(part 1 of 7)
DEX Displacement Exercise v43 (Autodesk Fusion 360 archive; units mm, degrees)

design "DEX Displacement Exercise" references "rct-lb-perp-pincer-x", "rct-dex-toes", "RCT N17 Blister Mirror", "rct-dex-hearth", "rct-dex-squat", "rct-lb-perp-pincer-t", "rct-lb-gt3-edge-idler", "rct-lb-gt3-endmatter", "dex-fixtures-typefive", "RCT N17 Blister"
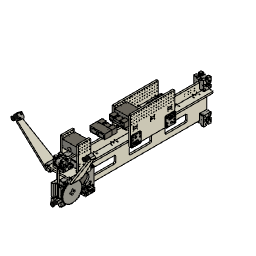
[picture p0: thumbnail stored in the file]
parameter "t_sheet_MAIN" = 6.7 comment "thickness of *most* of the gantry material"
parameter "t_sheet_SECOND" = 6.35 (= "1 / 4 * 1") comment "thickness of the webs"
parameter "od_bearings" = 16
parameter "id_bearings" = 5
parameter "t_bearings" = 5
parameter "p_belt" = 2
parameter "w_belt" = 10
parameter "t_belt" = 1.4
parameter "l_top_belt_to_rail" = 3
parameter "r_cutoutTool" = 2.05 (= "4.1 mm / 2")
parameter "hw_m3_thru" = 3.5
parameter "hw_m3_head" = 5.5
parameter "hw_m3_washer" = 7
parameter "hw_m3_thread" = 2.5
parameter "tab_breather" = 0.2 comment "tab clearance"
parameter "hw_m5_thread" = 4.2
parameter "hw_m5_head" = 8.5
parameter "hw_m5_washer" = 10
parameter "hw_m5_thru" = 5.25
parameter "hw_m6_thru" = 6.5
parameter "hw_m6_head" = 10
parameter "hw_m6_washer" = 12
parameter "l_beltblock" = 15
parameter "hw_plstf6_thread" = 2.94
parameter "hw_plstf6_thru" = 4
parameter "hw_plstf6_head" = 6.86
parameter "hw_plstf6_washer" = 7.92
parameter "hw_m3_flathead" = 6
parameter "hw_m4insert_d" = 6
parameter "hw_m4insert_l" = 4.8
parameter "hw_m4_tappedwj" = 3.3
parameter "hw_m4_thru" = 4.25
parameter "hw_m4_head" = 7
parameter "hw_m4_headheight" = 4
parameter "preload_bearings" = 0.55
parameter "hw_m3insert_d" = 5.4
parameter "hw_m3insert_l" = 3.8
parameter "dist_clearance" = 0.5
parameter "hw_shoulder_headDiameter" = 9
parameter "hw_shoulder_headHeight" = 4
parameter "l_travel" = 385 comment "will be rounded to 10s"
parameter "User Parameter" = 0 (= "min 10")
parameter "nh_rail_width" = "nh_gantry_width - 3"
parameter "l_shoulder_thread" = 10
parameter "hw_n6_thru" = 4.064
parameter "hw_n6_thread" = 3.1
parameter "hw_n6_flathead" = 6.6548
parameter "hw_n6_head" = 6.858
parameter "carriage_offsets" = 0.25
parameter "hw_momentPin_reald" = 3.683
parameter "d285" = 2
parameter "d344" = 3.5
parameter "d482" = 3.35 (= "t_sheet_MAIN / 2")
parameter "d578" = 0.5
parameter "d683" = 3.683 (= "hw_momentPin_reald")
parameter "d689" = 0.5
parameter "d698" = 5
parameter "d705" = 3.5415 (= "d683 / 2 + 1.7 mm")
parameter "d837" = 0.25
parameter "d1052" = 1.5
parameter "d1488" = 23.5592 (= "d1487 / 2 + d1486 / 2 + 2.4 mm")
parameter "d1496" = 0.3 (= "d1494")
sketch "Basics" plane through (0, 0, 0) normal (0, 1, 0) x axis (1, 0, 0)
  line L1 (-3.35, -35.65) -> (3.35, -35.65)
  line L2 (-3.35, 98.35) -> (-3.35, -35.65)
  line L3 (3.35, 98.35) -> (-3.35, 98.35)
  line L4 (3.35, -35.65) -> (3.35, 98.35)
  line L5 (-29.1, -3.35) -> (-3.35, -3.35)
  line L6 (-29.1, 3.35) -> (-29.1, -3.35)
  line L7 (-3.35, 3.35) -> (-29.1, 3.35)
  line L8 (-3.35, -3.35) -> (-3.35, 3.35)
  line L9 (-19.35, -35.15) -> (-3.35, -35.15)
  line L10 (-19.35, -30.15) -> (-19.35, -35.15)
  line L11 (-3.35, -30.15) -> (-19.35, -30.15)
  line L12 (-3.35, -35.15) -> (-3.35, -30.15)
  line L13 (19.35, -30.15) -> (3.35, -30.15)
  line L14 (19.35, -35.15) -> (19.35, -30.15)
  line L15 (3.35, -35.15) -> (19.35, -35.15)
  line L16 (3.35, -30.15) -> (3.35, -35.15)
  line L17 (2.5, -35.65) -> (-2.5, -35.65)
  line L18 (2.5, -51.65) -> (2.5, -35.65)
  line L19 (-2.5, -51.65) -> (2.5, -51.65)
  line L20 (-2.5, -35.65) -> (-2.5, -51.65)
  line L21 (-30.1, -36.65) -> (19.9, -36.65)
  line L22 (-30.1, -43.35) -> (-30.1, -36.65)
  line L23 (19.9, -43.35) -> (-30.1, -43.35)
  line L24 (19.9, -36.65) -> (19.9, -43.35)
  line L25 (-30.1, -93.35) -> (-36.8, -93.35)
  line L26 (-30.1, 19.9) -> (-30.1, -93.35)
  line L27 (-36.8, 19.9) -> (-30.1, 19.9)
  line L28 (-36.8, -93.35) -> (-36.8, 19.9)
  line L29 (-45.1, 2.5) -> (-29.1, 2.5)
  line L30 (-45.1, -2.5) -> (-45.1, 2.5)
  line L31 (-29.1, -2.5) -> (-45.1, -2.5)
  line L32 (-29.1, 2.5) -> (-29.1, -2.5)
  line L33 (-23.6, 3.35) -> (-28.6, 3.35)
  line L34 (-23.6, 19.35) -> (-23.6, 3.35)
  line L35 (-28.6, 19.35) -> (-23.6, 19.35)
  line L36 (-28.6, 3.35) -> (-28.6, 19.35)
  line L37 (-23.6, -3.35) -> (-28.6, -3.35)
  line L38 (-23.6, -19.35) -> (-23.6, -3.35)
  line L39 (-28.6, -19.35) -> (-23.6, -19.35)
  line L40 (-28.6, -3.35) -> (-28.6, -19.35)
  line L41 (-15.85, -25.65) -> (-15.85, -30.15)
  line L42 (-6.85, -25.65) -> (-15.85, -25.65)
  line L43 (-6.85, -30.15) -> (-6.85, -25.65)
  point P10 (-3.35, -35.15)
  point P14 (3.35, -30.15)
  point P22 (0, -35.65)
  point P35 (-28.6, 3.35)
  point P39 (-29.1, 0)
  point P40 (-28.6, -3.35)
  point P37 (-23.6, 19.35)
  point P44 (-15.85, -30.15)
  point P47 (-6.85, -30.15)
  point P48 (-11.35, -25.65)
  point P49 (-11.35, -30.15)
  point P9 (-3.35, 3.35)
  point P1 (0, 0)
  point P25 (-30.1, -43.35)
  point P50 (19.9, -40)
  point P7 (-29.1, -3.35)
  point P8 (-29.1, 3.35)
  point P11 (-19.35, -35.15)
  point P12 (-19.35, -30.15)
  point P13 (-3.35, -30.15)
  point P3 (-3.35, -35.65)
  point P45 (-15.85, -25.65)
  point P46 (-6.85, -25.65)
  point P26 (19.9, -43.35)
  point P19 (2.5, -35.65)
  horizontal L1
  vertical L2
  horizontal L3
  vertical L4
  horizontal L5
  vertical L6
  horizontal L7
  horizontal L9
  vertical L10
  horizontal L11
  vertical L12
  coincident L2 P10
  horizontal L13
  vertical L14
  horizontal L15
  vertical L16
  coincident L4 P14
  horizontal L17
  vertical L18
  horizontal L19
  vertical L20
  equal L10 L19
  equal L10 L14
  equal L9 L20
  equal L9 L15
  coincident P10 L15
  midpoint L17 P22
  midpoint L1 P22
  horizontal L21
  vertical L22
  horizontal L23
  vertical L24
  vertical L26
  horizontal L27
  vertical L28
  equal L6 L27
  equal L6 L22
  horizontal L29
  vertical L30
  horizontal L31
  vertical L32
  horizontal L33
  vertical L34
  horizontal L35
  vertical L36
  equal L30 L35
  equal L10 L35
  equal L29 L36
  equal L11 L36
  coincident L7 P35
  midpoint L32 P39
  midpoint L6 P39
  horizontal L37
  vertical L38
  horizontal L39
  vertical L40
  equal L35 L39
  equal L34 L40
  coincident L5 P40
  coincident P37 L38
  vertical L8
  coincident L11 P44
  perpendicular L11 L41
  perpendicular L41 L42
  coincident L11 P47
  perpendicular L11 L43
  midpoint L42 P48
  midpoint L11 P49
  vertical P48 P49
  coincident L2 P9
  vertical P1 P22
  horizontal P1 P39
  coincident P25 L26
  midpoint L24 P50
  horizontal L25
  dimension "d925" distance P7 P8 = 6.7 (= "t_sheet_MAIN")
  dimension "d926" distance L2 L4 = 6.7 (= "t_sheet_MAIN")
  dimension "d928" distance P11 P12 = 5 (= "t_bearings")
  dimension "d929" distance P12 P13 = 16 (= "od_bearings")
  dimension "d930" distance P3 L9 = 0.5
  dimension "d932" distance P11 L21 = 1.5 (= "d1052")
  dimension "d935" distance P8 L36 = 0.5
  dimension "d936" distance L26 L36 = 1.5 (= "d1052")
  dimension "d1049" distance P44 P45 = 4.5
  dimension "d1050" distance P45 P46 = 9
  dimension "d1055" distance P22 P26 = 19.9
  dimension "d1056" distance L27 P39 = 19.9
  dimension "d1099" distance L3 P9 = 95
  dimension "d1213" distance P26 L26 = 50
  dimension "d1214" distance P25 L25 = 50
  dimension "d1215" distance P39 P50 = 40
  dimension "d1241" distance L2 L26 = 26.75
  dimension "d1583" distance P1 P39 = 29.1
  dimension "d1584" distance P1 P19 = 35.65
  dimension "d1012" OffsetX = 0
  dimension "d1013" OffsetY = 0
  dimension "d1014" OffsetZ = 0
  dimension "d1015" AngleZ = 0
  dimension "d1036" OffsetX = 0
  dimension "d1037" OffsetY = 0
  dimension "d1038" OffsetZ = 0
  dimension "d1039" AngleZ = 0
  dimension "d1061" OffsetX = 0
  dimension "d1062" OffsetY = 0
  dimension "d1063" OffsetZ = 0
  dimension "d1064" AngleZ = 0
  dimension "d900" distance = 6
  dimension "d902" distance = 3.7 (= "2 mm + 1.2 mm + 0.5 mm")
  dimension "d903" distance = 1
  dimension "d904" distance = 8
  dimension "d905" distance = 2.54
  dimension "d906" distance = 2.54
  dimension "d907" distance = 2.54
  dimension "d908" Side1Offset = 0
  dimension "d909" TaperAngle = 0
  dimension "d910" ProfileOffset = 0
  dimension "d911" Side1Offset = 0
  dimension "d912" TaperAngle = 0
  dimension "d913" leftDistance = 1.5
  dimension "d915" distance = 5.65
  dimension "d916" distance = 14.65
  dimension "d917" distance = 14.65
  dimension "d918" Side1Offset = 0
  dimension "d919" TaperAngle = 0
  dimension "d920" ChordLen = 4
  dimension "d921" ChordLen = 1
  dimension "d923" distance = 2.54
  dimension "d924" Radius = 2
  dimension "d729" diameter = 4
  dimension "d730" diameter = 6 (= "hw_m4insert_d")
  dimension "d731" diameter = 16 (= "od_bearings")
  dimension "d732" distance = 1
  dimension "d733" distance = 0.25
  dimension "d734" AlongDistance = -26
  dimension "d735" TaperAngle = 0
  dimension "d736" ProfileOffset = 0.5
  dimension "d737" AlongDistance = 5 (= "t_bearings")
  dimension "d738" TaperAngle = 0
  dimension "d739" distance = 6
  dimension "d740" ProfileOffset = 0
  dimension "d741" Side1Offset = 0
  dimension "d742" TaperAngle = 0
  dimension "d743" Radius = 4
  dimension "d744" distance = -1
  dimension "d745" AlongDistance = 32
  dimension "d746" TaperAngle = 0
  dimension "d747" distance = 0.5
  dimension "d748" distance = 1
  dimension "d749" ProfileOffset = 0
  dimension "d750" AlongDistance = 3
  dimension "d751" TaperAngle = 0
  dimension "d752" ProfileOffset = 0
  dimension "d753" Side1Offset = 0
  dimension "d754" TaperAngle = 0
  dimension "d755" Side1Offset = 0
  dimension "d756" TaperAngle = 0
  dimension "d757" ProfileOffset = 0
  dimension "d758" Side1Offset = 0
  dimension "d759" TaperAngle = 0
  dimension "d760" AlongDistance = 12
  dimension "d761" TaperAngle = 0
  dimension "d762" AlongDistance = -37
  dimension "d763" TaperAngle = 0
  dimension "d764" Side1Offset = 0.5
  dimension "d765" TaperAngle = 0
  dimension "d767" Radius = 3
  dimension "d768" Radius = 2
  dimension "d770" Radius = 3
  dimension "d771" Radius = 3
  dimension "d772" distance = 3
  dimension "d773" distance = 3
  dimension "d774" Radius = 1
  dimension "d775" Radius = 0.5
  dimension "d776" Radius = 2
  dimension "d777" diameter = 5.4 (= "hw_m3insert_d")
  dimension "d778" diameter = 3.5 (= "hw_m3_thru")
  dimension "d779" Side1Offset = 0
  dimension "d780" TaperAngle = 0
  dimension "d781" Side1Offset = 0
  dimension "d782" TaperAngle = 0
  dimension "d783" Radius = 2
  dimension "d784" Radius = 2
  dimension "d785" Radius = 2
  dimension "d786" Radius = 3
  dimension "d788" Radius = 0.5
  dimension "d789" distance = 12
  dimension "d790" distance = 2
  dimension "d791" angle = 45
  dimension "d793" Radius = 2
  dimension "d794" Radius = 2
  dimension "d795" Radius = 1
  dimension "d797" Radius = 2
  dimension "d798" Radius = 1
  dimension "d799" Radius = 2
  dimension "d800" Radius = 4.5
  dimension "d801" distance = 0.275 (= "preload_bearings / 2")
  dimension "d803" distance = -0.5
  dimension "d806" distance = 3
  dimension "d807" AlongDistance = -60
  dimension "d808" distance = 3.8274 (= "d430 / 2")
  dimension "d809" distance = 0.423 (= "1 mm - 0.577 mm")
  dimension "d810" distance = 0.5
  dimension "d813" Side1Offset = 0
  dimension "d814" TaperAngle = 0
  dimension "d815" distance = 0.1
  dimension "d816" distance = 1.75
  dimension "d818" distance = 35
  dimension "d820" distance = 5
  dimension "d821" distance = 5
  dimension "d822" diameter = 4.064 (= "hw_n6_thru")
  dimension "d823" diameter = 6.6548 (= "hw_n6_flathead")
  dimension "d824" distance = 0.6
  dimension "d825" distance = 0.6 (= "d824")
  dimension "d827" TaperAngle = 0
  dimension "d828" diameter = 3.1 (= "hw_n6_thread")
  dimension "d829" Side1Offset = 0
  dimension "d830" TaperAngle = 0
  dimension "d831" distance = 4
  dimension "d832" distance = 4.477 (= "d833")
  dimension "d833" distance = 4.477 (= "d477")
  dimension "d836" diameter = 6.6548 (= "hw_n6_flathead")
  dimension "d839" Side1Offset = 0
  dimension "d840" TaperAngle = 0
  dimension "d841" distance = 0.9
  dimension "d842" angle = 50
  dimension "d843" angle = 50
  dimension "d844" distance = 8
  dimension "d845" distance = 5
  dimension "d846" diameter = 4.5
  dimension "d847" AlongDistance = -7
  dimension "d848" TaperAngle = 0
  dimension "d849" leftDistance = 0.75
  dimension "d850" ProfileOffset = 0
  dimension "d851" Side1Offset = 0
  dimension "d852" TaperAngle = 0
  dimension "d853" ProfileOffset = 0
  dimension "d854" Side1Offset = 0
  dimension "d855" TaperAngle = 0
  dimension "d856" distance = 12.7
  dimension "d857" leftDistance = 1.5
  dimension "d858" distance = 1.5454
  dimension "d859" Radius = 4
  dimension "d860" Radius = 2
  dimension "d861" Radius = 2
  dimension "d862" Radius = 4
  dimension "d863" Radius = 2
  dimension "d864" Radius = 35
  dimension "d865" Radius = 4
  dimension "d866" Radius = 1
  dimension "d869" Side1Offset = 0
  dimension "d870" TaperAngle = 0
  dimension "d872" distance = 1.5
  dimension "d873" leftDistance = 1.5
  dimension "d874" Radius = 2
  dimension "d885" distance = 27.775
  dimension "d886" distance = 30.275 (= "30 mm + preload_bearings / 2")
  dimension "d889" diameter = 3.3 (= "hw_m4_tappedwj")
  dimension "d890" distance = 5
  dimension "d891" distance = 10.275 (= "10 mm + preload_bearings / 2")
  dimension "d893" TaperAngle = 0
  dimension "d894" distance = 17.5
  dimension "d895" distance = 27.5
  dimension "d896" distance = 0.2
  dimension "d897" distance = 0.2 (= "d896")
extrude "Extrude1" new body sketch "Basics" profile of L3 L5 L6 L7 L8 along normal blind 600 (= "l_actual_complete") OffsetX 0 OffsetY 0 OffsetZ 0 AngleZ 0 OffsetX 0 OffsetY 0 OffsetZ 0 AngleZ 0 OffsetX 0 OffsetY 0 OffsetZ 0 AngleZ 0 OffsetX 0 OffsetY 0 OffsetZ 0 AngleZ 0 bodies "dex-rail_left-wing"
extrude "Extrude2" new body sketch "Basics" profile of L1 L2 L3 L4 L5 along normal blind 600 (= "l_actual_complete")
extrude "Extrude1" new body sketch "Basics" profile of L21 L25 L26 L27 L28 along normal blind 90 (= "( nh_gantry_length * 10 ) * 1 mm / 2") OffsetX 0 OffsetY 0 OffsetZ 0 AngleZ 0
extrude "Extrude2" new body sketch "Basics" profile of L21 L22 L23 L24 L25 along normal blind 90 (= "( nh_gantry_length * 10 ) * 1 mm / 2")
ground "Ground1"
joint "Assemble4" alignAngle 0 alignOffsetX 0 alignOffsetY 0 alignOffsetZ 0 DistanceMinimum 95 DistanceMaximum 390 (= "l_actual_complete - ( nh_gantry_length * 10 ) * 1 mm - 30 mm")
sketch "Sketch2" plane through (0, -166.9996, 43.35) normal (0, 0, 1) x axis (-1, 0, 0)
  line L1 (-19.9, -166.9996) -> (30.1, -166.9996)
  line L2 (-19.9, -256.9996) -> (-19.9, -166.9996)
  line L3 (30.1, -256.9996) -> (-19.9, -256.9996)
  line L4 (30.1, -166.9996) -> (30.1, -256.9996)
  line L5 (0, -256.9996) -> (0, -166.9996)
  line L6 (20, -194.9996) -> (-19.9, -194.9996)
  line L7 (20, -218.9996) -> (20, -194.9996)
  line L8 (2, -218.9996) -> (20, -218.9996)
  line L9 (2, -224.9996) -> (2, -218.9996)
  line L10 (-12, -224.9996) -> (2, -224.9996)
  line L11 (-12, -218.9996) -> (-12, -224.9996)
  line L12 (-19.9, -218.9996) -> (-12, -218.9996)
  line L13 (-30.1, -256.9996) -> (-19.9, -256.9996)
  line L14 (-30.1, -166.9996) -> (-30.1, -256.9996)
  line L15 (-19.9, -166.9996) -> (-30.1, -166.9996)
  line L16 (7.5, -186.9996) -> (7.5, -166.9996)
  line L17 (-7.5, -186.9996) -> (7.5, -186.9996)
  line L18 (-7.5, -166.9996) -> (-7.5, -186.9996)
  line L19 (-20.4, -218.9996) -> (-19.9, -218.9996)
  line L20 (-20.4, -194.9996) -> (-20.4, -218.9996)
  line L21 (-19.9, -194.9996) -> (-20.4, -194.9996)
  line L22 (16, -174.9996) -> (16, -166.9996)
  line L23 (8, -174.9996) -> (16, -174.9996)
  line L24 (8, -186.9996) -> (8, -174.9996)
  line L25 (-8, -186.9996) -> (8, -186.9996)
  line L26 (-8, -174.9996) -> (-8, -186.9996)
  line L27 (-16, -174.9996) -> (-8, -174.9996)
  line L28 (-16, -166.9996) -> (-16, -174.9996)
  circle C1 centre (5, -191.9996) radius 1.575
  circle C2 centre (15, -191.9996) radius 1.575
  circle C3 centre (-5, -191.9996) radius 1.575
  circle C4 centre (-15, -191.9996) radius 1.575
  circle C5 centre (-15, -221.9996) radius 1.575
  circle C6 centre (5, -221.9996) radius 1.575
  circle C7 centre (15, -221.9996) radius 1.575
  circle C8 centre (12, -181.9996) radius 1.575
  circle C9 centre (12, -171.9996) radius 1.575
  circle C10 centre (12, -181.9996) radius 2.7
  circle C11 centre (-12, -181.9996) radius 1.575
  circle C12 centre (-12, -171.9996) radius 1.575
  point P8 (0, -166.9996)
  point P9 (0, -256.9996)
  point P1 (0, 0)
  point P6 (5, -191.9996)
  point P7 (15, -191.9996)
  point P10 (-5, -191.9996)
  point P11 (-15, -191.9996)
  point P12 (-15, -221.9996)
  point P13 (5, -221.9996)
  point P14 (15, -221.9996)
  point P15 (-19.9, -194.9996)
  point P22 (-19.9, -218.9996)
  point P18 (2, -218.9996)
  point P4 (-19.9, -256.9996)
  point P23 (-19.9, -256.9996)
  point P3 (-19.9, -166.9996)
  point P26 (-19.9, -166.9996)
  point P27 (7.5, -166.9996)
  point P30 (-7.5, -166.9996)
  point P31 (0, -186.9996)
  point P33 (12, -171.9996)
  point P34 (12, -181.9996)
  point P39 (-19.9, -194.9996)
  point P40 (16, -166.9996)
  point P47 (-16, -166.9996)
  point P48 (0, -186.9996)
  point P42 (8, -174.9996)
  point P2 (30.1, -166.9996)
  point P28 (7.5, -186.9996)
  point P29 (-7.5, -186.9996)
  point P32 (12, -181.9996)
  point P37 (-20.4, -218.9996)
  point P41 (16, -174.9996)
  point P43 (8, -186.9996)
  coincident L1 P8
  coincident L3 P9
  perpendicular L3 L5
  coincident P1 L5
  horizontal P6 P7
  equal C1 C2
  horizontal P6 P10
  horizontal P6 P11
  equal C1 C7
  equal C1 C6
  equal C1 C5
  equal C1 C3
  equal C1 C4
  vertical P11 P12
  vertical P6 P13
  vertical P7 P14
  horizontal P13 P14
  horizontal P12 P14
  coincident L2 P15
  perpendicular L2 L6
  perpendicular L6 L7
  perpendicular L7 L8
  perpendicular L8 L9
  perpendicular L9 L10
  perpendicular L10 L11
  coincident L2 P22
  perpendicular L2 L12
  coincident P18 L12
  coincident P4 P23
  perpendicular L2 L13
  perpendicular L13 L14
  perpendicular L14 L15
  coincident P3 P26
  coincident L1 P27
  perpendicular L1 L16
  perpendicular L16 L17
  coincident L1 P30
  perpendicular L1 L18
  midpoint L17 P31
  vertical P8 P31
  equal C1 C8
  equal C8 C9
  concentric C8 C10
  vertical P33 P34
  symmetric L5 C8 C11
  symmetric L5 C9 C12
  perpendicular L2 L19
  perpendicular L19 L20
  perpendicular L20 L21
  coincident P15 P39
  coincident L1 P40
  perpendicular L1 L22
  perpendicular L16 L23
  perpendicular L23 L24
  perpendicular L5 L25
  perpendicular L25 L26
  perpendicular L26 L27
  coincident L1 P47
  perpendicular L1 L28
  midpoint L25 P48
  coincident L5 P48
  coincident P42 L27
  dimension "d1100" distance P6 L5 = 5
  dimension "d1101" diameter C1 = 3.15
  dimension "d1102" distance P6 P7 = 10
  dimension "d1103" distance P6 P8 = 25
  dimension "d1104" distance P8 P10 = 5
  dimension "d1105" distance P10 P11 = 10
  dimension "d1106" distance P7 P14 = 30
  dimension "d1107" distance P13 L9 = 3
  dimension "d1108" distance P13 L10 = 3
  dimension "d1109" distance P13 L8 = 3
  dimension "d1110" distance P12 L11 = 3
  dimension "d1111" distance P14 L7 = 5
  dimension "d1112" distance P7 L6 = 3
  dimension "d1218" distance P2 L14 = 60.2
  dimension "d1321" distance P28 P29 = 15
  dimension "d1322" distance P29 P30 = 20
  dimension "d1323" distance P32 P33 = 10
  dimension "d1324" distance L1 P33 = 5
  dimension "d1325" diameter C10 = 5.4 (= "hw_m3insert_d")
  dimension "d1326" distance L5 P32 = 12
  dimension "d1387" distance P22 P37 = 0.5
  dimension "d1449" distance P31 L24 = 8
  dimension "d1450" distance P40 P41 = 8
  dimension "d1451" distance P8 L22 = 16
  dimension "d1452" distance P8 L28 = 16 (= "d1451")
  dimension "d1453" distance P42 P43 = 12
extrude "Extrude3" cut sketch "Sketch2" profile of L2 C1 C2 C3 C4 C5 C6 C7 L6 L7 L8 L9 L10 L11 L12 C8 C9 C11 C12 no distance stored
extrude "Extrude5" add sketch "Sketch2" profile of L2 L13 L14 L15 L19 L20 L21 no distance stored
sketch "Sketch3" plane through (-36.8, 0, 0) normal (-1, 0, 0) x axis (0, -1, 0)
  line L1 (0, 93.35) -> (0, -19.9)
  line L2 (-90, 93.35) -> (0, 93.35)
  line L3 (-90, -19.9) -> (-90, 93.35)
  line L4 (0, -19.9) -> (-90, -19.9)
  line L5 (0, 0) -> (-90, 0)
  line L6 (-5, 15) -> (-5, -15)
  line L7 (-32, -12) -> (-38, -12)
  line L8 (-32, -19.9) -> (-32, -12)
  line L9 (-38, 12) -> (-38, -12)
  line L10 (-32, 12) -> (-38, 12)
  line L11 (-32, 20.5) -> (-32, 12)
  line L12 (-8, 20.5) -> (-32, 20.5)
  line L13 (-8, -19.9) -> (-8, 20.5)
  line L14 (-90, 40) -> (0, 40)
  line L15 (-90, 36.65) -> (-90, 43.35)
  line L16 (-12.5, 36.65) -> (-27.5, 36.65)
  line L17 (-12.5, 43.35) -> (-12.5, 36.65)
  line L18 (-27.5, 43.35) -> (-12.5, 43.35)
  line L19 (-27.5, 36.65) -> (-27.5, 43.35)
  line L20 (-12.5, 32.5) -> (-27.5, 32.5)
  line L21 (-12.5, 47.5) -> (-12.5, 32.5)
  line L22 (-27.5, 47.5) -> (-12.5, 47.5)
  line L23 (-27.5, 32.5) -> (-27.5, 47.5)
  line L24 (-82.5, 36.65) -> (-97.5, 36.65)
  line L25 (-82.5, 43.35) -> (-82.5, 36.65)
  line L26 (-97.5, 43.35) -> (-82.5, 43.35)
  line L27 (-97.5, 36.65) -> (-97.5, 43.35)
  line L28 (-82.5, 32.5) -> (-97.5, 32.5)
  line L29 (-82.5, 47.5) -> (-82.5, 32.5)
  line L30 (-97.5, 47.5) -> (-82.5, 47.5)
  line L31 (-97.5, 32.5) -> (-97.5, 47.5)
  circle C1 centre (-5, 5) radius 1.575
  circle C2 centre (-5, 15) radius 1.575
  circle C3 centre (-35, 15) radius 1.575
  circle C4 centre (-35, -15) radius 1.575
  circle C5 centre (-5, -15) radius 1.575
  circle C6 centre (-5, -5) radius 1.575
  circle C7 centre (-12.5, 32.5) radius 1.575
  circle C8 centre (-27.5, 32.5) radius 1.575
  circle C9 centre (-27.5, 47.5) radius 1.575
  circle C10 centre (-12.5, 47.5) radius 1.575
  circle C11 centre (-82.5, 32.5) radius 1.575
  circle C12 centre (-97.5, 32.5) radius 1.575
  circle C13 centre (-97.5, 47.5) radius 1.575
  circle C14 centre (-82.5, 47.5) radius 1.575
  point P6 (-90, 0)
  point P7 (0, 0)
  point P1 (0, 0)
  point P12 (-5, -15)
  point P14 (-5, -15)
  point P9 (-5, 15)
  point P15 (-5, 15)
  point P16 (-5, 0)
  point P13 (-5, -5)
  point P8 (-5, 5)
  point P11 (-35, -15)
  point P10 (-35, 15)
  point P19 (-32, -19.9)
  point P24 (-8, -19.9)
  point P25 (0, 40)
  point P26 (-90, 40)
  point P33 (-27.5, 40)
  point P37 (-12.5, 47.5)
  point P40 (-12.5, 47.5)
  point P35 (-27.5, 32.5)
  point P38 (-27.5, 32.5)
  point P34 (-12.5, 32.5)
  point P39 (-12.5, 32.5)
  point P36 (-27.5, 47.5)
  point P41 (-27.5, 47.5)
  point P46 (-97.5, 32.5)
  point P47 (-82.5, 32.5)
  point P50 (-97.5, 40)
  point P51 (-97.5, 40)
  point P32 (-27.5, 43.35)
  point P52 (-82.5, 32.5)
  point P53 (-97.5, 32.5)
  point P49 (-97.5, 47.5)
  point P54 (-97.5, 47.5)
  point P48 (-82.5, 47.5)
  point P55 (-82.5, 47.5)
  point P18 (-32, -12)
  point P56 (-90, 47.5)
  point P57 (-20, 32.5)
  point P29 (-27.5, 36.65)
  point P30 (-12.5, 36.65)
  coincident L3 P6
  coincident L1 P7
  perpendicular L1 L5
  coincident P1 L5
  coincident P12 P14
  vertical L6
  coincident P9 P15
  midpoint L6 P16
  coincident L5 P16
  coincident P13 L6
  coincident P8 L6
  equal C5 C6
  equal C1 C5
  equal C2 C5
  equal C4 C5
  equal C3 C5
  horizontal P11 P12
  horizontal P9 P10
  vertical P10 P11
  parallel L5 L7
  coincident L4 P19
  perpendicular L4 L8
  perpendicular L5 L9
  perpendicular L9 L10
  perpendicular L5 L11
  perpendicular L11 L12
  coincident L4 P24
  perpendicular L4 L13
  coincident L1 P25
  coincident L3 P26
  perpendicular L3 L14
  midpoint P26 L15
  horizontal L16
  vertical L17
  horizontal L18
  vertical L19
  midpoint L19 P33
  coincident L14 P33
  horizontal L20
  vertical L21
  horizontal L22
  vertical L23
  coincident P37 P40
  coincident P35 P38
  equal C8 C9
  equal C7 C8
  equal C8 C10
  coincident P34 P39
  coincident P36 P41
  coincident L17 P34
  horizontal L24
  vertical L25
  horizontal L26
  vertical L27
  horizontal L28
  vertical L29
  horizontal L30
  vertical L31
  coincident L27 P46
  coincident L25 P47
  midpoint L27 P50
  midpoint L31 P51
  coincident P50 P51
  coincident P32 L26
  coincident P36 L30
  equal L22 L30
  coincident L14 P51
  coincident P47 P52
  coincident P46 P53
  coincident P49 P54
  coincident P48 P55
  equal C8 C11
  equal C11 C12
  equal C11 C13
  equal C11 C14
  coincident P18 L11
  midpoint L30 P56
  coincident L3 P56
  midpoint L20 P57
  dimension "d1159" distance P12 P13 = 10
  dimension "d1160" distance P7 L6 = 5
  dimension "d1161" distance P8 P9 = 10
  dimension "d1162" diameter C5 = 3.15
  dimension "d1163" distance P13 P16 = 5
  dimension "d1164" distance P9 P10 = 30
  dimension "d1165" distance P11 L8 = 3
  dimension "d1166" distance P11 L7 = 3
  dimension "d1167" distance P11 L9 = 3
  dimension "d1170" distance P10 L12 = 5.5
  dimension "d1171" distance P8 L13 = 3
  dimension "d1269" distance P29 P30 = 15
  dimension "d1270" distance P29 P32 = 6.7 (= "t_sheet_MAIN")
  dimension "d1272" distance P38 P41 = 15
  dimension "d1273" distance P38 P39 = 15
  dimension "d1274" diameter C8 = 3.15
  dimension "d1276" distance L14 L20 = 7.5
  dimension "d1301" = 40
  dimension "d1388" distance P10 L10 = 3
  dimension "d1700" distance L1 P57 = 20
extrude "Extrude4" cut sketch "Sketch3" profile of L4 C1 C2 C3 C4 C5 C6 L7 L8 L9 L10 L11 L12 L13 no distance stored
sketch "Sketch6" plane through (0, 0, 43.35) normal (0, 0, 1) x axis (-1, 0, 0)
  line L1 (30.1, -90) -> (-30.1, -90)
  line L2 (30.1, 0) -> (30.1, -90)
  line L3 (-30.1, 0) -> (30.1, 0)
  line L4 (-30.1, -90) -> (-30.1, 0)
  line L5 (20, -28) -> (-20.4, -28)
  line L6 (20, -52) -> (20, -28)
  line L7 (2, -52) -> (20, -52)
  line L8 (2, -58) -> (2, -52)
  line L9 (-12, -58) -> (2, -58)
  line L10 (-12, -52) -> (-12, -58)
  line L11 (-20.4, -52) -> (-12, -52)
  line L12 (19.6, -32.5) -> (25.1, -32.5)
  line L13 (19.6, -30.5) -> (19.6, -32.5)
  line L14 (25.1, -30.5) -> (19.6, -30.5)
  line L15 (25.1, -32.5) -> (25.1, -30.5)
  line L16 (19.6, -9.5) -> (25.1, -9.5)
  line L17 (19.6, -7.5) -> (19.6, -9.5)
  line L18 (25.1, -7.5) -> (19.6, -7.5)
  line L19 (25.1, -9.5) -> (25.1, -7.5)
  line L20 (35.8, -27.2013) -> (35.8, -20)
  line L21 (30.1, -27.7) -> (35.8, -27.2013)
  line L22 (25.1, -20) -> (35.8, -20)
  line L23 (35.8, -12.7987) -> (35.8, -20)
  line L24 (30.1, -12.3) -> (35.8, -12.7987)
  line L25 (30.1, -97.7) -> (35.8, -97.2013)
  line L26 (25.1, -79.5) -> (25.1, -77.5)
  line L27 (19.6, -79.5) -> (25.1, -79.5)
  line L28 (19.6, -77.5) -> (19.6, -79.5)
  line L29 (35.8, -97.2013) -> (35.8, -90)
  line L30 (35.8, -82.7987) -> (35.8, -90)
  line L31 (19.6, -100.5) -> (19.6, -102.5)
  line L32 (19.6, -102.5) -> (25.1, -102.5)
  line L33 (25.1, -90) -> (35.8, -90)
  line L34 (25.1, -77.5) -> (19.6, -77.5)
  line L35 (25.1, -102.5) -> (25.1, -100.5)
  line L36 (25.1, -100.5) -> (19.6, -100.5)
  line L37 (30.1, -82.3) -> (35.8, -82.7987)
  line L38 (0, 0) -> (0, -90)
  line L39 (-25.1, -20) -> (-35.8, -20)
  line L40 (-19.6, -79.5) -> (-25.1, -79.5)
  line L41 (-25.1, -102.5) -> (-25.1, -100.5)
  line L42 (-19.6, -7.5) -> (-19.6, -9.5)
  line L43 (-35.8, -12.7987) -> (-35.8, -20)
  line L44 (-25.1, -7.5) -> (-19.6, -7.5)
  line L45 (-35.8, -27.2013) -> (-35.8, -20)
  line L46 (-25.1, -90) -> (-35.8, -90)
  line L47 (-19.6, -102.5) -> (-25.1, -102.5)
  line L48 (-19.6, -32.5) -> (-25.1, -32.5)
  line L49 (-30.1, -82.3) -> (-35.8, -82.7987)
  line L50 (-25.1, -30.5) -> (-19.6, -30.5)
  line L51 (-30.1, -27.7) -> (-35.8, -27.2013)
  line L52 (-25.1, -32.5) -> (-25.1, -30.5)
  line L53 (-19.6, -9.5) -> (-25.1, -9.5)
  line L54 (-35.8, -82.7987) -> (-35.8, -90)
  line L55 (-30.1, -97.7) -> (-35.8, -97.2013)
  line L56 (-25.1, -100.5) -> (-19.6, -100.5)
  line L57 (-25.1, -77.5) -> (-19.6, -77.5)
  line L58 (-19.6, -77.5) -> (-19.6, -79.5)
  line L59 (-20, -52) -> (-20, -28)
  line L60 (-35.8, -97.2013) -> (-35.8, -90)
  line L61 (-19.6, -30.5) -> (-19.6, -32.5)
  line L62 (-25.1, -9.5) -> (-25.1, -7.5)
  line L63 (-30.1, -12.3) -> (-35.8, -12.7987)
  line L64 (-25.1, -79.5) -> (-25.1, -77.5)
  line L65 (-19.6, -100.5) -> (-19.6, -102.5)
  line L66 (-20.4, -28) -> (-20.4, -52)
  circle C1 centre (-15, -55) radius 1.575
  circle C2 centre (15, -25) radius 1.575
  circle C3 centre (5, -25) radius 1.575
  circle C4 centre (-15, -25) radius 1.575
  circle C5 centre (15, -55) radius 1.575
  circle C6 centre (5, -55) radius 1.575
  circle C7 centre (-5, -25) radius 1.575
  circle C8 centre (25.1, -20) radius 1.575
  arc A1 centre (30.1436, -28.1981) radius 0.5 clockwise from (30.1, -28.6962) to (30.1, -27.7)
  arc A2 centre (30.1436, -11.8019) radius 0.5 clockwise from (30.1, -12.3) to (30.1, -11.3038)
  arc A3 centre (30.1436, -98.1981) radius 0.5 clockwise from (30.1, -98.6962) to (30.1, -97.7)
  arc A4 centre (30.1436, -81.8019) radius 0.5 clockwise from (30.1, -82.3) to (30.1, -81.3038)
  circle C9 centre (25.1, -90) radius 1.575
  arc A5 centre (-30.1436, -11.8019) radius 0.5 clockwise from (-30.1, -11.3038) to (-30.1, -12.3)
  arc A6 centre (-30.1436, -98.1981) radius 0.5 clockwise from (-30.1, -97.7) to (-30.1, -98.6962)
  circle C10 centre (-25.1, -20) radius 1.575
  circle C11 centre (-25.1, -90) radius 1.575
  arc A7 centre (-30.1436, -28.1981) radius 0.5 clockwise from (-30.1, -27.7) to (-30.1, -28.6962)
  arc A8 centre (-30.1436, -81.8019) radius 0.5 clockwise from (-30.1, -81.3038) to (-30.1, -82.3)
  circle C12 centre (-12, -5) radius 1.575
  circle C13 centre (12, -15) radius 1.575
  circle C14 centre (-12, -15) radius 1.575
  circle C15 centre (12, -5) radius 1.575
  point P21 (25.1, -20)
  point P32 (30.1, -27.7)
  point P33 (25.1, -20)
  point P34 (30.1, -28.6962)
  point P30 (35.8, -20)
  point P36 (35.8, -20)
  point P31 (35.8, -27.2013)
  point P37 (35.8, -12.7987)
  point P38 (30.1, -12.3)
  point P40 (30.1, -11.3038)
  point P42 (25.1, -90)
  point P41 (25.1, -90)
  point P53 (35.8, -90)
  point P58 (35.8, -90)
  point P55 (35.8, -97.2013)
  point P60 (35.8, -82.7987)
  point P54 (30.1, -97.7)
  point P59 (30.1, -82.3)
  point P51 (30.1, -98.6962)
  point P56 (30.1, -81.3038)
  point P61 (0, -90)
  point P62 (0, -90)
  point P63 (0, 0)
  point P3 (30.1, -90)
  point P83 (-30.1, -90)
  point P8 (20, -28)
  point P87 (-20, -28)
  point P9 (20, -52)
  point P64 (-20, -52)
  point P18 (15, -55)
  point P96 (-15, -55)
  point P22 (25.1, -32.5)
  point P94 (-25.1, -32.5)
  point P23 (19.6, -32.5)
  point P103 (-19.6, -32.5)
  point P24 (19.6, -30.5)
  point P69 (-19.6, -30.5)
  point P25 (25.1, -30.5)
  point P106 (-25.1, -30.5)
  point P26 (25.1, -9.5)
  point P84 (-25.1, -9.5)
  point P27 (19.6, -9.5)
  point P65 (-19.6, -9.5)
  point P28 (19.6, -7.5)
  point P82 (-19.6, -7.5)
  point P29 (25.1, -7.5)
  point P88 (-25.1, -7.5)
  point P99 (-35.8, -20)
  point P98 (-35.8, -27.2013)
  point P95 (-30.1, -27.7)
  point P102 (-25.1, -20)
  point P68 (-30.1, -28.6962)
  point P92 (-35.8, -20)
  point P71 (-35.8, -12.7987)
  point P91 (-30.1, -12.3)
  point P70 (-30.1, -11.3038)
  point P97 (-25.1, -90)
  point P43 (25.1, -100.5)
  point P104 (-25.1, -100.5)
  point P44 (25.1, -102.5)
  point P105 (-25.1, -102.5)
  point P45 (19.6, -102.5)
  point P81 (-19.6, -102.5)
  point P46 (19.6, -100.5)
  point P73 (-19.6, -100.5)
  point P47 (25.1, -77.5)
  point P100 (-25.1, -77.5)
  point P48 (19.6, -79.5)
  point P78 (-19.6, -79.5)
  point P49 (25.1, -79.5)
  point P93 (-25.1, -79.5)
  point P50 (19.6, -77.5)
  point P90 (-19.6, -77.5)
  point P86 (-30.1, -98.6962)
  point P101 (-35.8, -90)
  point P85 (-30.1, -97.7)
  point P76 (-35.8, -97.2013)
  point P74 (-30.1, -81.3038)
  point P75 (-35.8, -90)
  point P80 (-30.1, -82.3)
  point P79 (-35.8, -82.7987)
  point P4 (30.1, 0)
  horizontal L12
  vertical L13
  horizontal L14
  vertical L15
  horizontal L16
  vertical L17
  horizontal L18
  vertical L19
  equal L12 L16
  coincident P21 L15
  coincident P21 L19
  equal L15 L19
  vertical L20
  coincident L2 P32
  perpendicular L20 L22
  coincident P21 P33
  tangent L21 A1
  coincident L2 P34
  symmetric P30 L22 P36
  symmetric P31 L22 P37
  symmetric P32 L22 P38
  symmetric L22 P34 P40
  symmetric L22 A1 A2
  horizontal L32
  vertical L31
  horizontal L36
  vertical L35
  horizontal L27
  vertical L28
  horizontal L34
  vertical L26
  equal L27 L32
  coincident P42 L35
  coincident P42 L26
  equal L26 L35
  vertical L29
  perpendicular L29 L33
  coincident P41 P42
  tangent L25 A3
  symmetric P53 P58 L33
  symmetric P55 P60 L33
  symmetric P54 P59 L33
  symmetric P51 P56 L33
  symmetric A3 L33 A4
  coincident P31 L30
  coincident L2 P54
  coincident L2 P56
  vertical P21 P42
  midpoint L1 P61
  coincident P61 P62
  perpendicular L1 L38
  coincident L3 P63
  symmetric P3 L38 P83
  symmetric P8 L38 P87
  symmetric P9 L38 P64
  symmetric P18 L38 P96
  symmetric C8 L38 C10
  symmetric P22 L38 P94
  symmetric P23 L38 P103
  symmetric P24 L38 P69
  symmetric P25 L38 P106
  symmetric P26 L38 P84
  symmetric P27 L38 P65
  symmetric P28 L38 P82
  symmetric P29 L38 P88
  symmetric P30 L38 P99
  symmetric P31 L38 P98
  symmetric P32 L38 P95
  symmetric P33 L38 P102
  symmetric P34 L38 P68
  symmetric A1 L38 A7
  symmetric P36 L38 P92
  symmetric P37 L38 P71
  symmetric P38 L38 P91
  symmetric P40 L38 P70
  symmetric A2 L38 A5
  symmetric P41 L38 P97
  symmetric P43 L38 P104
  symmetric P44 L38 P105
  symmetric P45 L38 P81
  symmetric P46 L38 P73
  symmetric P47 L38 P100
  symmetric P48 L38 P78
  symmetric P49 L38 P93
  symmetric P50 L38 P90
  symmetric P51 L38 P86
  symmetric P53 L38 P101
  symmetric P54 L38 P85
  symmetric P55 L38 P76
  symmetric P56 L38 P74
  symmetric P58 L38 P75
  symmetric P59 L38 P80
  symmetric P60 L38 P79
  symmetric A3 L38 A6
  symmetric A4 L38 A8
  symmetric C9 L38 C11
  coincident L1 P42
  dimension "d1251" distance P4 P21 = 5
  dimension "d1252" diameter C8 = 3.15
  dimension "d1253" distance L3 P21 = 20
  dimension "d1259" distance P22 P23 = 5.5
  dimension "d1260" distance P22 P25 = 2
  dimension "d1261" distance L12 P28 = 25
  dimension "d1262" distance P21 L12 = 12.5
  dimension "d1263" distance L2 L20 = 5.7 (= "t_sheet_MAIN - 1 mm")
  dimension "d1264" distance P32 L22 = 7.7
  dimension "d1265" angle L20 L21 = 85
  dimension "d1266" radius A1 = 0.5
  dimension "d1292" diameter C9 = 3.15
  dimension "d1293" distance P44 P45 = 5.5
  dimension "d1294" distance P43 P44 = 2
  dimension "d1295" distance P50 L32 = 25
  dimension "d1296" distance P42 L32 = 12.5
  dimension "d1297" distance P54 L33 = 7.7
  dimension "d1298" angle L25 L29 = 85
  dimension "d1299" radius A3 = 0.5
extrude "Extrude10" cut sketch "Sketch6" profile of L1 L2 L4 L5 L6 L7 L8 L9 L10 L11 C1 C2 C3 C4 C5 C6 C7 C8 L12 L13 L14 L15 L16 L17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 no distance stored
extrude "Extrude11" new body sketch "Sketch6" profile of L2 L4 L20 L21 L23 L24 L30 L33 L37 L43 L45 L46 L49 L51 L54 L63 no distance stored
extrude "Extrude12" cut sketch "Sketch3" profile of L16 L17 L18 L19 C7 C8 C9 C10 L24 L25 L26 L27 C11 C12 C13 C14 no distance stored
combine "Combine5"
fillet "Fillet4" radius 0.5
work_plane "WorkPlane1"
mirror "Mirror3"
fillet "Fillet5" radius 0.5
extrude "Extrude16" cut sketch "Sketch2" profile of L1 C9 C12 L22 L23 L24 L25 L26 L27 L28 no distance stored
fillet "Fillet10" radius 3
fillet "Fillet11" radius 1
mirror "Mirror1"
combine "Combine1"
mirror "Mirror4"
combine "Combine3"
combine "Combine4"
fillet "Fillet6" radius 1
fillet "Fillet7" radius 1
sketch "Sketch1" plane through (-3.35, 0, 0) normal (-1, 0, 0) x axis (0, -1, 0)
  line L1 (0, 35.65) -> (0, -98.35)
  line L2 (-600, 35.65) -> (0, 35.65)
  line L3 (-600, -98.35) -> (-600, 35.65)
  line L4 (0, -98.35) -> (-600, -98.35)
  line L5 (-42.5, -7.5) -> (-57.5, -7.5)
  line L6 (-42.5, 7.5) -> (-42.5, -7.5)
  line L7 (-57.5, 7.5) -> (-42.5, 7.5)
  line L8 (-57.5, -7.5) -> (-57.5, 7.5)
  line L9 (-42.5, -3.35) -> (-57.5, -3.35)
  line L10 (-42.5, 3.35) -> (-42.5, -3.35)
  line L11 (-57.5, 3.35) -> (-42.5, 3.35)
  line L12 (-57.5, -3.35) -> (-57.5, 3.35)
  circle C1 centre (-57.5, -7.5) radius 1.575
  circle C2 centre (-42.5, -7.5) radius 1.575
  circle C3 centre (-57.5, 7.5) radius 1.575
  circle C4 centre (-42.5, 7.5) radius 1.575
  point P9 (-42.5, 7.5)
  point P12 (-42.5, 7.5)
  point P6 (-57.5, -7.5)
  point P10 (-57.5, -7.5)
  point P8 (-57.5, 7.5)
  point P13 (-57.5, 7.5)
  point P7 (-42.5, -7.5)
  point P11 (-42.5, -7.5)
  point P14 (-50, -7.5)
  point P15 (-42.5, 0)
  point P1 (0, 0)
  point P18 (-42.5, 3.35)
  point P16 (-57.5, -3.35)
  point P20 (-57.5, 0)
  point P21 (-57.5, 0)
  horizontal L5
  vertical L6
  horizontal L7
  vertical L8
  coincident P9 P12
  coincident P6 P10
  coincident P8 L7
  coincident P8 P13
  coincident P7 P11
  midpoint L5 P14
  equal C1 C3
  equal C1 C2
  equal C1 C4
  midpoint L6 P15
  horizontal P1 P15
  horizontal L9
  vertical L10
  horizontal L11
  vertical L12
  coincident L6 P18
  coincident L8 P16
  midpoint L12 P20
  midpoint L8 P21
  coincident P20 P21
  dimension "d1327" diameter C1 = 3.15
  dimension "d1328" distance L1 P14 = 50
  dimension "d1329" distance P10 P13 = 15
  dimension "d1330" distance P12 P13 = 15
  dimension "d1331" distance L9 L11 = 6.7 (= "t_sheet_MAIN")
extrude "Extrude3" cut sketch "Sketch1" profile of C1 C2 C3 C4 L9 L10 L11 L12 no distance stored
rectangular_pattern "R-Pattern1" uSpaceDistance -500 (= "-l_actual_complete + 100 mm") vSpaceDistance 0
sketch "Sketch2" plane through (0, 0, 3.35) normal (0, 0, 1) x axis (-1, 0, 0)
  line L1 (3.35, 0) -> (29.1, 0)
  line L2 (3.35, -600) -> (3.35, 0)
  line L3 (29.1, -600) -> (3.35, -600)
  line L4 (29.1, 0) -> (29.1, -600)
  line L5 (0.5, -54.8507) -> (3.35, -55.1)
  line L6 (0.5, -45.1493) -> (0.5, -54.8507)
  line L7 (3.35, -44.9) -> (0.5, -45.1493)
  line L8 (13.85, -60.5) -> (8.35, -60.5)
  line L9 (13.85, -62.5) -> (13.85, -60.5)
  line L10 (8.35, -62.5) -> (13.85, -62.5)
  line L11 (8.35, -60.5) -> (8.35, -62.5)
  line L12 (13.85, -39.5) -> (8.35, -39.5)
  line L13 (13.85, -37.5) -> (13.85, -39.5)
  line L14 (8.35, -37.5) -> (13.85, -37.5)
  line L15 (8.35, -39.5) -> (8.35, -37.5)
  circle C1 centre (8.35, -50) radius 1.575
  arc A1 centre (3.3064, -55.5981) radius 0.5 clockwise from (3.35, -55.1) to (3.35, -56.0962)
  arc A2 centre (3.3064, -44.4019) radius 0.5 clockwise from (3.35, -43.9038) to (3.35, -44.9)
  point P7 (3.35, -55.1)
  point P10 (3.35, -44.9)
  point P11 (0.5, -50)
  point P6 (8.35, -50)
  point P12 (3.35, -56.0962)
  point P14 (3.35, -43.9038)
  point P20 (8.35, -39.5)
  point P17 (13.85, -60.5)
  point P1 (0, 0)
  point P18 (13.85, -62.5)
  point P19 (8.35, -62.5)
  coincident L2 P7
  parallel L2 L6
  coincident L2 P10
  midpoint L6 P11
  horizontal P6 P11
  tangent L5 A1
  coincident L2 P12
  tangent L7 A2
  coincident L2 P14
  horizontal L8
  vertical L9
  horizontal L10
  vertical L11
  horizontal L12
  vertical L13
  horizontal L14
  vertical L15
  coincident P6 L11
  coincident L11 P20
  equal L9 L13
  coincident P17 L13
  dimension "d1339" distance L2 L6 = 2.85 (= "t_sheet_MAIN / 2 - 0.5 mm")
  dimension "d1340" distance P1 P6 = 50
  dimension "d1341" distance L2 P6 = 5
  dimension "d1342" diameter C1 = 3.15
  dimension "d1343" angle L5 L6 = 85
  dimension "d1344" angle L6 L7 = 85
  dimension "d1345" radius A1 = 0.5
  dimension "d1346" radius A2 = 0.5
  dimension "d1347" distance P7 P10 = 10.2
  dimension "d1348" distance P17 P18 = 2
  dimension "d1349" distance P18 P19 = 5.5
  dimension "d1350" distance P18 L14 = 25
  dimension "d1351" distance P6 L10 = 12.5 (= "d1350 / 2")
extrude "Extrude4" cut sketch "Sketch2" profile of L2 C1 A1 A2 L8 L9 L10 L11 L12 L13 L14 L15 no distance stored
extrude "Extrude5" new body sketch "Sketch2" profile of L2 L5 L6 L7 no distance stored
rectangular_pattern "R-Pattern2" uSpaceDistance 500 (= "l_actual_complete - 100 mm") vSpaceDistance 0
fillet "Fillet2" radius 0.5
combine "Combine1"
sketch "Sketch4" plane through (0, 0, 3.35) normal (0, 0, 1) x axis (-1, 0, 0)
  line L1 (8.35, -456.1667) -> (13.85, -456.1667)
  line L2 (8.35, -454.1667) -> (8.35, -456.1667)
  line L3 (13.85, -454.1667) -> (8.35, -454.1667)
  line L4 (13.85, -456.1667) -> (13.85, -454.1667)
  line L5 (13.85, -479.1667) -> (13.85, -477.1667)
  line L6 (8.35, -479.1667) -> (13.85, -479.1667)
  line L7 (8.35, -477.1667) -> (8.35, -479.1667)
  line L8 (13.85, -477.1667) -> (8.35, -477.1667)
  line L9 (8.35, -289.5) -> (13.85, -289.5)
  line L10 (8.35, -287.5) -> (8.35, -289.5)
  line L11 (13.85, -287.5) -> (8.35, -287.5)
  line L12 (13.85, -289.5) -> (13.85, -287.5)
  line L13 (13.85, -312.5) -> (13.85, -310.5)
  line L14 (8.35, -312.5) -> (13.85, -312.5)
  line L15 (8.35, -310.5) -> (8.35, -312.5)
  line L16 (13.85, -310.5) -> (8.35, -310.5)
  line L17 (8.35, -122.8333) -> (13.85, -122.8333)
  line L18 (8.35, -120.8333) -> (8.35, -122.8333)
  line L19 (13.85, -120.8333) -> (8.35, -120.8333)
  line L20 (13.85, -122.8333) -> (13.85, -120.8333)
  line L21 (13.85, -145.8333) -> (13.85, -143.8333)
  line L22 (8.35, -145.8333) -> (13.85, -145.8333)
  line L23 (8.35, -143.8333) -> (8.35, -145.8333)
  line L24 (13.85, -143.8333) -> (8.35, -143.8333)
  line L25 (13.85, -62.5) -> (13.85, -60.5)
  line L26 (8.35, -62.5) -> (13.85, -62.5)
  line L27 (8.35, -60.5) -> (8.35, -62.5)
  line L28 (13.85, -60.5) -> (8.35, -60.5)
  line L29 (8.35, -39.5) -> (13.85, -39.5)
  line L30 (8.35, -37.5) -> (8.35, -39.5)
  line L31 (13.85, -37.5) -> (8.35, -37.5)
  line L32 (13.85, -39.5) -> (13.85, -37.5)
  line L33 (13.85, -229.1667) -> (13.85, -227.1667)
  line L34 (8.35, -229.1667) -> (13.85, -229.1667)
  line L35 (8.35, -227.1667) -> (8.35, -229.1667)
  line L36 (13.85, -227.1667) -> (8.35, -227.1667)
  line L37 (8.35, -206.1667) -> (13.85, -206.1667)
  line L38 (8.35, -204.1667) -> (8.35, -206.1667)
  line L39 (13.85, -204.1667) -> (8.35, -204.1667)
  line L40 (13.85, -206.1667) -> (13.85, -204.1667)
  line L41 (13.85, -395.8333) -> (13.85, -393.8333)
  line L42 (8.35, -395.8333) -> (13.85, -395.8333)
  line L43 (8.35, -393.8333) -> (8.35, -395.8333)
  line L44 (13.85, -393.8333) -> (8.35, -393.8333)
  line L45 (8.35, -372.8333) -> (13.85, -372.8333)
  line L46 (8.35, -370.8333) -> (8.35, -372.8333)
  line L47 (13.85, -370.8333) -> (8.35, -370.8333)
  line L48 (13.85, -372.8333) -> (13.85, -370.8333)
  line L49 (13.85, -562.5) -> (13.85, -560.5)
  line L50 (8.35, -562.5) -> (13.85, -562.5)
  line L51 (8.35, -560.5) -> (8.35, -562.5)
  line L52 (13.85, -560.5) -> (8.35, -560.5)
  line L53 (8.35, -539.5) -> (13.85, -539.5)
  line L54 (8.35, -537.5) -> (8.35, -539.5)
  line L55 (13.85, -537.5) -> (8.35, -537.5)
  line L56 (13.85, -539.5) -> (13.85, -537.5)
  line L57 (0.5, -545.1493) -> (3.35, -544.9)
  line L58 (0.5, -554.8507) -> (0.5, -545.1493)
  line L59 (3.35, -555.1) -> (0.5, -554.8507)
  line L60 (3.35, -600) -> (3.35, -556.4375)
  line L61 (29.1, -600) -> (3.35, -600)
  line L62 (29.1, 0) -> (29.1, -600)
  line L63 (3.35, 0) -> (29.1, 0)
  line L64 (3.35, -43.5625) -> (3.35, 0)
  line L65 (0.5, -45.1493) -> (3.35, -44.9)
  line L66 (0.5, -54.8507) -> (0.5, -45.1493)
  line L67 (3.35, -55.1) -> (0.5, -54.8507)
  line L68 (3.35, -126.8959) -> (3.35, -56.4375)
  line L69 (0.5, -128.4827) -> (3.35, -128.2333)
  line L70 (0.5, -138.184) -> (0.5, -128.4827)
  line L71 (3.35, -138.4333) -> (0.5, -138.184)
  line L72 (3.35, -210.2292) -> (3.35, -139.7708)
  line L73 (0.5, -211.816) -> (3.35, -211.5667)
  line L74 (0.5, -221.5173) -> (0.5, -211.816)
  line L75 (3.35, -221.7667) -> (0.5, -221.5173)
  line L76 (3.35, -293.5625) -> (3.35, -223.1041)
  line L77 (0.5, -295.1493) -> (3.35, -294.9)
  line L78 (0.5, -304.8507) -> (0.5, -295.1493)
  line L79 (3.35, -305.1) -> (0.5, -304.8507)
  line L80 (3.35, -376.8959) -> (3.35, -306.4375)
  line L81 (0.5, -378.4827) -> (3.35, -378.2333)
  line L82 (0.5, -388.184) -> (0.5, -378.4827)
  line L83 (3.35, -388.4333) -> (0.5, -388.184)
  line L84 (3.35, -460.2292) -> (3.35, -389.7708)
  line L85 (0.5, -461.816) -> (3.35, -461.5667)
  line L86 (0.5, -471.5173) -> (0.5, -461.816)
  line L87 (3.35, -471.7667) -> (0.5, -471.5173)
  line L88 (3.35, -543.5625) -> (3.35, -473.1041)
  line L89 (44.1, 0) -> (29.1, 0)
  line L90 (44.1, -40) -> (44.1, 0)
  line L91 (29.1, -40) -> (44.1, -40)
  circle C1 centre (8.35, -466.6667) radius 1.575
  circle C2 centre (8.35, -300) radius 1.575
  circle C3 centre (8.35, -133.3333) radius 1.575
  circle C4 centre (8.35, -50) radius 1.575
  circle C5 centre (8.35, -216.6667) radius 1.575
  circle C6 centre (8.35, -383.3333) radius 1.575
  circle C7 centre (8.35, -550) radius 1.575
  arc A1 centre (3.85, -543.5625) radius 0.5 clockwise from (3.5782, -543.9822) to (3.35, -543.5625)
  arc A2 centre (3.3064, -544.4019) radius 0.5 clockwise from (3.5782, -543.9822) to (3.35, -544.9)
  arc A3 centre (3.3064, -555.5981) radius 0.5 clockwise from (3.35, -555.1) to (3.5782, -556.0178)
  arc A4 centre (3.85, -556.4375) radius 0.5 clockwise from (3.35, -556.4375) to (3.5782, -556.0178)
  arc A5 centre (3.85, -43.5625) radius 0.5 clockwise from (3.5782, -43.9822) to (3.35, -43.5625)
  arc A6 centre (3.3064, -44.4019) radius 0.5 clockwise from (3.5782, -43.9822) to (3.35, -44.9)
  arc A7 centre (3.3064, -55.5981) radius 0.5 clockwise from (3.35, -55.1) to (3.5782, -56.0178)
  arc A8 centre (3.85, -56.4375) radius 0.5 clockwise from (3.35, -56.4375) to (3.5782, -56.0178)
  arc A9 centre (3.85, -126.8959) radius 0.5 clockwise from (3.5782, -127.3156) to (3.35, -126.8959)
  arc A10 centre (3.3064, -127.7352) radius 0.5 clockwise from (3.5782, -127.3156) to (3.35, -128.2333)
  arc A11 centre (3.3064, -138.9314) radius 0.5 clockwise from (3.35, -138.4333) to (3.5782, -139.3511)
  arc A12 centre (3.85, -139.7708) radius 0.5 clockwise from (3.35, -139.7708) to (3.5782, -139.3511)
  arc A13 centre (3.85, -210.2292) radius 0.5 clockwise from (3.5782, -210.6489) to (3.35, -210.2292)
  arc A14 centre (3.3064, -211.0686) radius 0.5 clockwise from (3.5782, -210.6489) to (3.35, -211.5667)
  arc A15 centre (3.3064, -222.2648) radius 0.5 clockwise from (3.35, -221.7667) to (3.5782, -222.6844)
  arc A16 centre (3.85, -223.1041) radius 0.5 clockwise from (3.35, -223.1041) to (3.5782, -222.6844)
  arc A17 centre (3.85, -293.5625) radius 0.5 clockwise from (3.5782, -293.9822) to (3.35, -293.5625)
  arc A18 centre (3.3064, -294.4019) radius 0.5 clockwise from (3.5782, -293.9822) to (3.35, -294.9)
  arc A19 centre (3.3064, -305.5981) radius 0.5 clockwise from (3.35, -305.1) to (3.5782, -306.0178)
  arc A20 centre (3.85, -306.4375) radius 0.5 clockwise from (3.35, -306.4375) to (3.5782, -306.0178)
  arc A21 centre (3.85, -376.8959) radius 0.5 clockwise from (3.5782, -377.3156) to (3.35, -376.8959)
  arc A22 centre (3.3064, -377.7352) radius 0.5 clockwise from (3.5782, -377.3156) to (3.35, -378.2333)
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  point P79 (29.1, 0)
  point P153 (29.1, 0)
  point P156 (29.1, -40)
  point P154 (44.1, 0)
  point P155 (44.1, -40)
  point P158 (39.1, -35)
  point P157 (39.972, -5)
  coincident P79 P153
  perpendicular L62 L89
  perpendicular L63 L90
  coincident L62 P156
  perpendicular L62 L91
  dimension "d1662" distance P154 P155 = 40
  dimension "d1663" distance P153 P154 = 15
  dimension "d1664" distance L91 P158 = 5
  dimension "d1665" distance L89 P157 = 5
  dimension "d1666" distance L90 P158 = 5
  dimension "d1667" diameter = 3.15
extrude "Extrude7" add sketch "Sketch4" no distance stored
fillet "Fillet5" radius 2
mirror "Mirror2" bodies "dex-rail_right-wing"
